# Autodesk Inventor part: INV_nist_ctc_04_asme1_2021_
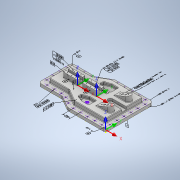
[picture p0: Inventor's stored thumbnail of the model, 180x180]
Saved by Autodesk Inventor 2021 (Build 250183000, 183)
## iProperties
Created: 2016-11
Part Number: INV_nist_ctc_04_asme1_2021_
Material: Generic
Document SubType Name: Modeling
Designer: t_liuje
Density: 1 g/cm^3
Appearance: Default
Author: t_liuje
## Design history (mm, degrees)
sketch "Sketch1"
  geometry: L1 (0, 0)-(-400.096, 0); L2 (-780, 75)-(-780, 425); L3 (-400.096, 500)-(0, 500); L4 (0, 500)-(0, 0); L5 (-400.096, 500)-(-530, 425); L6 (-400.096, 500)-(-250.096, 500); L7 (-530, 425)-(-780, 425); L8 (-400.096, 0)-(-530, 75); L9 (-530, 75)-(-780, 75)
  constraints: 18 end point, 4 horizontal, 3 equal length, 2 parallel, 1 perpendicular
  dimensions: "d5" = 780 distance between parallel lines of L4 L2; "d10" = 500 distance of L3.end L1.start; "d11" = 350 distance of L2.start L2.end; "d12" = 150 deg angle of L5 L7; "d13" = 150 deg angle of L9 L8 (= d12); "d14" = 250 distance of L8.end L2.start
extrude "Extrusion1" new body sketch "Sketch1" distance "d15" = 30; taper "d16" = 0 deg
sketch "Sketch2"
  geometry: L1 (-780, 425)-(-780, 75) reference; L2 (-780, 75)-(-530, 75) reference; L3 (-530, 75)-(-400.096, 0) reference; L4 (-400.096, 0)-(0, 0) reference; L5 (0, 0)-(0, 500) reference; L6 (0, 500)-(-400.096, 500) reference; L7 (-400.096, 500)-(-530, 425) reference; L8 (-530, 425)-(-780, 425) reference; L9 (-385.359, 445)-(-55, 445); L10 (-55, 445)-(-55, 55); L11 (-55, 55)-(-385.359, 55); L12 (-385.359, 55)-(-515.263, 130); L13 (-515.263, 130)-(-725, 130); L14 (-725, 130)-(-725, 370); L15 (-725, 370)-(-515.263, 370); L16 (-515.263, 370)-(-385.359, 445)
  constraints: 16 end point, 7 other
  dimensions: "d28" = 55 distance between parallel lines of L6 L9
extrude "Extrusion2" join sketch "Sketch2" distance "d29" = 40; taper "d30" = 0 deg
sketch "Sketch3"
  geometry: L1 (-655, 290)-(-505, 290); L2 (-505, 290)-(-505, 210); L3 (-505, 210)-(-655, 210); L4 (-655, 210)-(-655, 290); L5 (-455, 290)-(-305, 290); L6 (-305, 290)-(-305, 210); L7 (-305, 210)-(-455, 210); L8 (-455, 210)-(-455, 290); L9 (-780, 425)-(-780, 75) reference; L10 (-530, 425)-(-780, 425) reference; 1 further point
  constraints: 16 end point, 4 parallel, 2 horizontal, 2 perpendicular, 1 collinear
  dimensions: "d31" = 150 distance of L2.end L3.end; "d32" = 80 distance of L1.end L2.end; "d33" = 150 distance of L6.end L7.end (= d31); "d34" = 80 distance of L5.end L6.end (= d32); "d35" = 50 distance between parallel lines of L8 L2; "d36" = 125 distance between parallel lines of L9 L4; "d37" = 135 distance between parallel lines of L1 L10
extrude "Extrusion3" join sketch "Sketch3" distance "d38" = 50; taper "d39" = 0 deg
workplane "Work Plane2"
  workaxis "Work Axis1"
sketch "Sketch4"
  geometry: L1 (-225, 375)-(-105, 375); L2 (-105, 315)-(-225, 315); L3 (-225, 315)-(-225, 375); L4 (0, 0)-(0, 500) reference; L5 (0, 500)-(-400.096, 500) reference; L6 (-400.096, 0)-(0, 0) reference; L7 (-225, 185)-(-105, 185); L8 (-105, 125)-(-225, 125); L9 (-225, 125)-(-225, 185); A1 r 30 centre (-105, 345) between (-105, 315) and (-105, 375); A2 r 30 centre (-105, 155) between (-105, 125) and (-105, 185)
  constraints: 12 end point, 4 point on circle, 4 tangent, 2 centre point, 2 horizontal, 2 parallel
  dimensions: "d42" = 60 distance of L2.end L1.start; "d46" = 225 distance between parallel lines of L4 L3; "d47" = 120 distance from line of A1.centre L3; "d51" = 125 distance between parallel lines of L1 L5; "d54" = 60 distance of L8.end L7.start (= d42); "d55" = 120 distance from line of L9 A2.centre (= d47); "d56" = 125 distance between parallel lines of L6 L8 (= d51); "d57" = 225 distance between parallel lines of L4 L9 (= d46)
extrude "Extrusion4" join sketch "Sketch4" stored distance "d58" = 0; taper "d59" = 0 deg
sketch "Sketch5"
  geometry: L1 (-338.059, 171)-(-273, 171); L2 (-273, 171)-(-273, 96); L3 (-273, 96)-(-338.059, 96); L4 (-403, 117.981)-(-403, 149.019); L5 (-338.059, 96)-(-403, 117.981); L6 (-338.059, 171)-(-403, 149.019); L7 (-385.359, 55)-(-55, 55) reference; L8 (-55, 55)-(-55, 445) reference; L9 (-338.059, 404)-(-403, 382.019); L10 (-338.059, 404)-(-273, 404); L11 (-273, 404)-(-273, 329); L12 (-273, 329)-(-338.059, 329); L13 (-338.059, 329)-(-403, 350.981); L14 (-403, 350.981)-(-403, 382.019); L15 (-55, 445)-(-385.359, 445) reference; 1 further point
  constraints: 24 end point, 6 parallel, 2 horizontal, 2 perpendicular
  dimensions: "d61" = 75 distance of L1.end L2.end; "d62" = 161.3 deg angle of L1 L6; "d63" = 161.3 deg angle of L3 L5 (= d62); "d64" = 130 distance between parallel lines of L2 L4; "d65" = 65.059 distance of L1.start L1.end; "d66" = 41 distance between parallel lines of L3 L7; "d68" = 75 distance of L10.end L11.end; "d69" = 161.3 deg angle of L10 L9; "d70" = 161.3 deg angle of L12 L13 (= d69); "d71" = 130 distance between parallel lines of L11 L14; "d72" = 65.059 distance of L9.start L10.end; "d73" = 218 distance between parallel lines of L8 L2; "d74" = 218 distance between parallel lines of L8 L11 (= d73); "d75" = 41 distance between parallel lines of L10 L15 (= d66)
extrude "Extrusion5" cut sketch "Sketch5" distance "d76" = 26.25; taper "d77" = 0 deg
fillet "Fillet2" dims "d92" = 4
fillet "Fillet8" dims "d93" = 13
fillet "Fillet9" dims "d94" = 25
fillet "Fillet10" dims "d95" = 5
sketch "Sketch6"
  geometry: L1 (-200, 275)-(-55, 275); L2 (-55, 275)-(-55, 225); L3 (-55, 225)-(-200, 225); L4 (-381.876, 55)-(-68, 55) reference; L5 (-55, 68)-(-55, 432) reference; A1 r 25 centre (-200, 250) between (-200, 275) and (-200, 225); 1 further point
  constraints: 6 end point, 2 point on circle, 2 tangent, 1 centre point, 1 collinear, 1 horizontal, 1 parallel, 1 perpendicular
  dimensions: "d98" = 170 distance between parallel lines of L4 L3; "d99" = 145 distance from line of L2 A1.centre; "d100" = 50 distance between parallel lines of L3 L1
extrude "Extrusion6" cut sketch "Sketch6" distance "d101" = 25.125; taper "d102" = 0 deg
fillet "Fillet11" dims "d103" = 2.5
workplane "Work Plane3"
sketch "Sketch13"
  geometry: 31 further points
sketch "Sketch7"
  geometry: L1 (129.424, 5)-(13.347, 5); L2 (129.424, 255)-(13.347, 255); 11 further points
  constraints: 4 end point, 2 coincident
  dimensions: "d188" = 95 distance of point (129.424, 35) point (34.424, 35); "d189" = 30 distance from line of L1 point (34.424, 35); "d190" = 30 distance of point (129.424, 35) point (99.424, 35); "d191" = 35 distance of point (64.424, 35) point (99.424, 35)
sketch "Sketch14"
  geometry: A1 r 25 centre (755, 400) between (780, 400) and (755, 425) reference; 33 further points
  constraints: 1 coincident
hole "Hole22" sketch "Sketch14" diameter "d754" = 14; stored, may be unused: countersink angle "d758" = 90 deg, drill point angle "d760" = 118 deg; dims "d755" = 6, "d756" = 20, "d757" = 2, "d759" = 8
hole "Hole8" sketch "Sketch7" diameter "d172" = 10.106; stored, may be unused: countersink angle "d176" = 90 deg, drill point angle "d178" = 118 deg; dims "d173" = 25, "d174" = 4, "d175" = 2, "d177" = 25
hole "Hole10" sketch "Sketch7" diameter "d192" = 12; stored, may be unused: countersink angle "d196" = 90 deg, drill point angle "d198" = 118 deg; dims "d193" = 6, "d194" = 20, "d195" = 20, "d197" = 40.2
hole "Hole20" sketch "Sketch14" diameter "d678" = 14; stored, may be unused: countersink angle "d682" = 90 deg, drill point angle "d684" = 118 deg; dims "d679" = 6, "d680" = 20, "d681" = 2, "d683" = 8
hole "Hole21" sketch "Sketch14" diameter "d747" = 14; stored, may be unused: countersink angle "d751" = 90 deg, drill point angle "d753" = 118 deg; dims "d748" = 6, "d749" = 20, "d750" = 2, "d752" = 8
sketch "Sketch8"
  geometry: L1 (-671.016, 276.25)-(-285.042, 276.25); L2 (-671.016, 223.75)-(-285.042, 223.75); L3 (-625, 310.911)-(-625, 176.517); L4 (-580, 310.911)-(-580, 176.517); L5 (-535, 310.911)-(-535, 182.097); L6 (-425, 310.911)-(-425, 188.608); L7 (-380, 307.655)-(-380, 193.258); L8 (-335, 307.655)-(-335, 188.608); L9 (-655, 286)-(-655, 214) reference; L10 (-455, 286)-(-455, 214) reference; L11 (-651, 210)-(-509, 210) reference; 13 further points
  constraints: 24 point on line, 16 end point, 6 vertical, 2 horizontal
  dimensions: "d199" = 30 distance between parallel lines of L9 L3; "d200" = 45 distance between parallel lines of L4 L3; "d201" = 45 distance between parallel lines of L5 L4; "d202" = 30 distance between parallel lines of L10 L6; "d203" = 45 distance between parallel lines of L7 L6; "d204" = 45 distance between parallel lines of L8 L7; "d205" = 13.75 distance between parallel lines of L11 L2; "d206" = 52.5 distance between parallel lines of L2 L1
hole "Hole11" sketch "Sketch8" diameter "d207" = 6.647; stored, may be unused: countersink angle "d211" = 90 deg, drill point angle "d213" = 118 deg; dims "d208" = 6, "d209" = 20, "d210" = 20, "d212" = 25
hole "Hole19" sketch "Sketch8" diameter "d659" = 6.647; stored, may be unused: countersink angle "d663" = 90 deg, drill point angle "d665" = 118 deg; dims "d660" = 6, "d661" = 4, "d662" = 2, "d664" = 25
sketch "Sketch9"
  geometry: L1 (46, 48.5)-(21, 48.5); L2 (21, 23.5)-(46, 23.5); L3 (46, 23.5)-(46, 48.5); L4 (46, 76)-(0, 76) reference; L5 (46, 72)-(46, 0) reference; A1 r 12.5 centre (21, 36) between (21, 48.5) and (21, 23.5); 1 further point
  constraints: 6 end point, 2 point on circle, 2 tangent, 1 centre point, 1 collinear, 1 horizontal, 1 parallel
  dimensions: "d215" = 25 distance of L2.start L1.end; "d216" = 27.5 distance between parallel lines of L4 L1; "d218" = 25 distance from line of A1.centre L3
extrude "Extrusion7" cut sketch "Sketch9" stored distance "d219" = 25.125; taper "d220" = 0 deg
hole "Hole12" diameter "d223" = 10; stored, may be unused: countersink angle "d227" = 90 deg, drill point angle "d229" = 118 deg; dims "d221" = 12, "d222" = 52.5, "d224" = 6, "d225" = 20, "d226" = 20, "d228" = 25
hole "Hole13" diameter "d232" = 10; stored, may be unused: countersink angle "d236" = 90 deg, drill point angle "d238" = 118 deg; dims "d230" = 12, "d231" = 52.5, "d233" = 6, "d234" = 20, "d235" = 20, "d237" = 25
sketch "Sketch10"
  geometry: L1 (25, 0)-(393.397, 0) reference; L2 (405.897, 3.349)-(524.199, 71.651) reference; L3 (536.699, 75)-(755, 75) reference; L4 (780, 100)-(780, 400) reference; L5 (755, 425)-(536.699, 425) reference; L6 (393.397, 500)-(25, 500) reference; L7 (524.199, 428.349)-(405.897, 496.651) reference; L8 (0, 475)-(0, 25) reference; L9 (87.702, 70)-(379.404, 70); L10 (491.987, 135)-(687.702, 135); L11 (87.702, 210)-(687.702, 210); L12 (87.702, 210)-(87.702, 70); L13 (687.702, 210)-(687.702, 135); L14 (379.404, 70)-(491.987, 135); 1 further point
  constraints: 12 end point, 8 point on line, 4 parallel, 2 vertical
  dimensions: "d242" = 70 distance between parallel lines of L1 L9; "d243" = 60 distance between parallel lines of L3 L10; "d244" = 75 distance between parallel lines of L10 L11; "d245" = 87.702 distance between parallel lines of L8 L12; "d246" = 92.298 distance between parallel lines of L4 L13; "d247" = 70.968 distance between parallel lines of L2 L14
extrude "Extrusion8" cut sketch "Sketch10" distance "d248" = 15.811; taper "d249" = 0 deg
fillet "Fillet12" dims "d250" = 5
mirror "Mirror2"
sketch "Sketch11"
  geometry: L1 (-341.146, 145.064)-(-319.933, 123.851); L2 (-336.018, 148.422)-(-316.576, 128.979); L3 (-328.418, 149.307)-(-315.691, 136.579); L4 (-344.504, 139.936)-(-325.061, 120.494); L5 (-345.389, 132.337)-(-332.661, 119.609); 1 further point
  constraints: 10 end point, 1 midpoint, 12 other
body "Solid1"
node "Annotations"
node "Tolerance Features"
fillet "Fillet1" dims "d81" = 5
chamfer "Chamfer1" distance "d89" = 5; stored, may be unused: second distance "d90" = 2, angle "d91" = 45 deg
node "Projected Loop1"
workplane "Work Plane1"
node "Planar Surface 1" dims "d269" = 9.58338 (derived), "d270" = 5.20441 (derived), "d342" = 29.35731 (derived), "d343" = 1.74635 (derived), "d344" = -3.74843 (derived), "d345" = 10 (derived), "d642" = 28.40977 (derived), "d690" = 909.09523 (derived), "d691" = 910.05054 (derived), "d692" = 75 (derived), "d774" = 8.55047 (derived), "d775" = 6.5519 (derived), "d776" = 0.5 (derived), "d777" = 0 (derived), "d778" = 0 (derived), "d786" = 19.57161 (derived), "d787" = 5 (derived), "d788" = 1 (derived), "d790" = 0.75 (derived), "d791" = 50 (derived), "d792" = 0 (derived), "d793" = 3.45907 (derived), "d794" = 2.53074 (derived), "d795" = 5.54765 (derived)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
node "Datum Identifier 1" dims "d269" = 9.58338 (derived), "d270" = 5.20441 (derived), "d342" = 29.35731 (derived), "d343" = 1.74635 (derived), "d344" = -3.74843 (derived), "d345" = 10 (derived), "d642" = 28.40977 (derived), "d678" = 14, "d690" = 909.09523 (derived), "d691" = 910.05054 (derived), "d692" = 75 (derived), "d747" = 14, "d754" = 14, "d774" = 8.55047 (derived), "d775" = 6.5519 (derived), "d776" = 0.5 (derived), "d777" = 0 (derived), "d778" = 0 (derived), "d786" = 19.57161 (derived), "d787" = 5 (derived), "d788" = 1 (derived), "d790" = 0.75 (derived), "d791" = 50 (derived), "d792" = 0 (derived)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
node "Datum Reference Frame 1"
node "Diameter Dimension 3" dims "d345" = 10 (derived)
node "Coplanar Group 1"
node "Parallel Axes Pattern 14"
node "Hole Note 31"
node "Linear Dimension 1" dims "d692" = 75 (derived)
node "Simple Hole 185" dims "d269" = 9.58338 (derived), "d270" = 5.20441 (derived), "d342" = 29.35731 (derived), "d343" = 1.74635 (derived), "d344" = -3.74843 (derived), "d345" = 10 (derived), "d642" = 28.40977 (derived), "d690" = 909.09523 (derived), "d691" = 910.05054 (derived), "d692" = 75 (derived), "d774" = 8.55047 (derived), "d775" = 6.5519 (derived), "d776" = 0.5 (derived), "d777" = 0 (derived), "d778" = 0 (derived), "d786" = 19.57161 (derived), "d787" = 5 (derived), "d788" = 1 (derived), "d790" = 0.75 (derived), "d791" = 50 (derived), "d792" = 0 (derived), "d793" = 3.45907 (derived), "d794" = 2.53074 (derived), "d795" = 5.54765 (derived)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
node "Datum Reference Frame 22"
node "Simple Hole 186" dims "d269" = 9.58338 (derived), "d270" = 5.20441 (derived), "d342" = 29.35731 (derived), "d343" = 1.74635 (derived), "d344" = -3.74843 (derived), "d345" = 10 (derived), "d642" = 28.40977 (derived), "d690" = 909.09523 (derived), "d691" = 910.05054 (derived), "d692" = 75 (derived), "d774" = 8.55047 (derived), "d775" = 6.5519 (derived), "d776" = 0.5 (derived), "d777" = 0 (derived), "d778" = 0 (derived), "d786" = 19.57161 (derived), "d787" = 5 (derived), "d788" = 1 (derived), "d790" = 0.75 (derived), "d791" = 50 (derived), "d792" = 0 (derived), "d793" = 3.45907 (derived), "d794" = 2.53074 (derived), "d795" = 5.54765 (derived)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
node "Datum Reference Frame 23"
node "Datum Reference Frame 24"
node "Planar Surface 15"
node "Feature Control Frame 1"
node "Simple Hole 187"
node "Simple Hole 188"
node "Simple Hole 189"
node "Simple Hole 190"
node "Simple Hole 191"
node "Hole Note 32"
node "Feature Control Frame 3"
node "Planar Surface 16" dims "d269" = 9.58338 (derived), "d270" = 5.20441 (derived), "d342" = 29.35731 (derived), "d343" = 1.74635 (derived), "d344" = -3.74843 (derived), "d345" = 10 (derived), "d642" = 28.40977 (derived), "d690" = 909.09523 (derived), "d691" = 910.05054 (derived), "d692" = 75 (derived), "d774" = 8.55047 (derived), "d775" = 6.5519 (derived), "d776" = 0.5 (derived), "d777" = 0 (derived), "d778" = 0 (derived), "d786" = 19.57161 (derived), "d787" = 5 (derived), "d788" = 1 (derived), "d790" = 0.75 (derived), "d791" = 50 (derived), "d792" = 0 (derived), "d793" = 3.45907 (derived), "d794" = 2.53074 (derived), "d795" = 5.54765 (derived)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
node "Datum Identifier 19" dims "d269" = 9.58338 (derived), "d270" = 5.20441 (derived), "d342" = 29.35731 (derived), "d343" = 1.74635 (derived), "d344" = -3.74843 (derived), "d345" = 10 (derived), "d642" = 28.40977 (derived), "d678" = 14, "d690" = 909.09523 (derived), "d691" = 910.05054 (derived), "d692" = 75 (derived), "d747" = 14, "d754" = 14, "d774" = 8.55047 (derived), "d775" = 6.5519 (derived), "d776" = 0.5 (derived), "d777" = 0 (derived), "d778" = 0 (derived), "d786" = 19.57161 (derived), "d787" = 5 (derived), "d788" = 1 (derived), "d790" = 0.75 (derived), "d791" = 50 (derived), "d792" = 0 (derived)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
node "Datum Reference Frame 25"
node "Planar Surface 17" dims "d269" = 9.58338 (derived), "d270" = 5.20441 (derived), "d342" = 29.35731 (derived), "d343" = 1.74635 (derived), "d344" = -3.74843 (derived), "d345" = 10 (derived), "d642" = 28.40977 (derived), "d690" = 909.09523 (derived), "d691" = 910.05054 (derived), "d692" = 75 (derived), "d774" = 8.55047 (derived), "d775" = 6.5519 (derived), "d776" = 0.5 (derived), "d777" = 0 (derived), "d778" = 0 (derived), "d786" = 19.57161 (derived), "d787" = 5 (derived), "d788" = 1 (derived), "d790" = 0.75 (derived), "d791" = 50 (derived), "d792" = 0 (derived), "d793" = 3.45907 (derived), "d794" = 2.53074 (derived), "d795" = 5.54765 (derived)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
node "Datum Identifier 20" dims "d269" = 9.58338 (derived), "d270" = 5.20441 (derived), "d342" = 29.35731 (derived), "d343" = 1.74635 (derived), "d344" = -3.74843 (derived), "d345" = 10 (derived), "d642" = 28.40977 (derived), "d678" = 14, "d690" = 909.09523 (derived), "d691" = 910.05054 (derived), "d692" = 75 (derived), "d747" = 14, "d754" = 14, "d774" = 8.55047 (derived), "d775" = 6.5519 (derived), "d776" = 0.5 (derived), "d777" = 0 (derived), "d778" = 0 (derived), "d786" = 19.57161 (derived), "d787" = 5 (derived), "d788" = 1 (derived), "d790" = 0.75 (derived), "d791" = 50 (derived), "d792" = 0 (derived)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
node "Datum Reference Frame 26"
node "Planar Surface 18" dims "d269" = 9.58338 (derived), "d270" = 5.20441 (derived), "d342" = 29.35731 (derived), "d343" = 1.74635 (derived), "d344" = -3.74843 (derived), "d345" = 10 (derived), "d642" = 28.40977 (derived), "d690" = 909.09523 (derived), "d691" = 910.05054 (derived), "d692" = 75 (derived), "d774" = 8.55047 (derived), "d775" = 6.5519 (derived), "d776" = 0.5 (derived), "d777" = 0 (derived), "d778" = 0 (derived), "d786" = 19.57161 (derived), "d787" = 5 (derived), "d788" = 1 (derived), "d790" = 0.75 (derived), "d791" = 50 (derived), "d792" = 0 (derived), "d793" = 3.45907 (derived), "d794" = 2.53074 (derived), "d795" = 5.54765 (derived)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
node "Datum Identifier 21" dims "d269" = 9.58338 (derived), "d270" = 5.20441 (derived), "d342" = 29.35731 (derived), "d343" = 1.74635 (derived), "d344" = -3.74843 (derived), "d345" = 10 (derived), "d642" = 28.40977 (derived), "d678" = 14, "d690" = 909.09523 (derived), "d691" = 910.05054 (derived), "d692" = 75 (derived), "d747" = 14, "d754" = 14, "d774" = 8.55047 (derived), "d775" = 6.5519 (derived), "d776" = 0.5 (derived), "d777" = 0 (derived), "d778" = 0 (derived), "d786" = 19.57161 (derived), "d787" = 5 (derived), "d788" = 1 (derived), "d790" = 0.75 (derived), "d791" = 50 (derived), "d792" = 0 (derived)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
node "Datum Reference Frame 27"
node "Planar Surface 19" dims "d269" = 9.58338 (derived), "d270" = 5.20441 (derived), "d342" = 29.35731 (derived), "d343" = 1.74635 (derived), "d344" = -3.74843 (derived), "d345" = 10 (derived), "d642" = 28.40977 (derived), "d690" = 909.09523 (derived), "d691" = 910.05054 (derived), "d692" = 75 (derived), "d774" = 8.55047 (derived), "d775" = 6.5519 (derived), "d776" = 0.5 (derived), "d777" = 0 (derived), "d778" = 0 (derived), "d786" = 19.57161 (derived), "d787" = 5 (derived), "d788" = 1 (derived), "d790" = 0.75 (derived), "d791" = 50 (derived), "d792" = 0 (derived), "d793" = 3.45907 (derived), "d794" = 2.53074 (derived), "d795" = 5.54765 (derived)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
node "Datum Identifier 22" dims "d269" = 9.58338 (derived), "d270" = 5.20441 (derived), "d342" = 29.35731 (derived), "d343" = 1.74635 (derived), "d344" = -3.74843 (derived), "d345" = 10 (derived), "d642" = 28.40977 (derived), "d678" = 14, "d690" = 909.09523 (derived), "d691" = 910.05054 (derived), "d692" = 75 (derived), "d747" = 14, "d754" = 14, "d774" = 8.55047 (derived), "d775" = 6.5519 (derived), "d776" = 0.5 (derived), "d777" = 0 (derived), "d778" = 0 (derived), "d786" = 19.57161 (derived), "d787" = 5 (derived), "d788" = 1 (derived), "d790" = 0.75 (derived), "d791" = 50 (derived), "d792" = 0 (derived)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
node "Datum Reference Frame 28"
node "Planar Surface 20" dims "d269" = 9.58338 (derived), "d270" = 5.20441 (derived), "d342" = 29.35731 (derived), "d343" = 1.74635 (derived), "d344" = -3.74843 (derived), "d345" = 10 (derived), "d642" = 28.40977 (derived), "d690" = 909.09523 (derived), "d691" = 910.05054 (derived), "d692" = 75 (derived), "d774" = 8.55047 (derived), "d775" = 6.5519 (derived), "d776" = 0.5 (derived), "d777" = 0 (derived), "d778" = 0 (derived), "d786" = 19.57161 (derived), "d787" = 5 (derived), "d788" = 1 (derived), "d790" = 0.75 (derived), "d791" = 50 (derived), "d792" = 0 (derived), "d793" = 3.45907 (derived), "d794" = 2.53074 (derived), "d795" = 5.54765 (derived)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
node "Datum Identifier 23" dims "d269" = 9.58338 (derived), "d270" = 5.20441 (derived), "d342" = 29.35731 (derived), "d343" = 1.74635 (derived), "d344" = -3.74843 (derived), "d345" = 10 (derived), "d642" = 28.40977 (derived), "d678" = 14, "d690" = 909.09523 (derived), "d691" = 910.05054 (derived), "d692" = 75 (derived), "d747" = 14, "d754" = 14, "d774" = 8.55047 (derived), "d775" = 6.5519 (derived), "d776" = 0.5 (derived), "d777" = 0 (derived), "d778" = 0 (derived), "d786" = 19.57161 (derived), "d787" = 5 (derived), "d788" = 1 (derived), "d790" = 0.75 (derived), "d791" = 50 (derived), "d792" = 0 (derived)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
node "Datum Reference Frame 29"
node "Datum Reference Frame 30"
node "Datum Reference Frame 31"
node "Datum Reference Frame 32"
node "Simple Hole 192"
node "Simple Hole 193"
node "Simple Hole 194"
node "Simple Hole 195"
node "Simple Hole 196"
node "Simple Hole 197"
node "Parallel Axes Pattern 15"
node "Hole Note 33"
node "Feature Control Frame 4"
node "Planar Surface 21"
node "Planar Surface 22"
node "Feature Control Frame 5"
node "Leader Text 1"
node "Hole Note 34"
node "Hole Note 35"
node "Diameter Dimension 9" dims "d847" = 14 (derived)
node "Datum Identifier 26" dims "d269" = 9.58338 (derived), "d270" = 5.20441 (derived), "d342" = 29.35731 (derived), "d343" = 1.74635 (derived), "d344" = -3.74843 (derived), "d345" = 10 (derived), "d642" = 28.40977 (derived), "d678" = 14, "d690" = 909.09523 (derived), "d691" = 910.05054 (derived), "d692" = 75 (derived), "d747" = 14, "d754" = 14, "d774" = 8.55047 (derived), "d775" = 6.5519 (derived), "d776" = 0.5 (derived), "d777" = 0 (derived), "d778" = 0 (derived), "d786" = 19.57161 (derived), "d787" = 5 (derived), "d788" = 1 (derived), "d790" = 0.75 (derived), "d791" = 50 (derived), "d792" = 0 (derived)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
node "Diameter Dimension 10" dims "d851" = 14 (derived)
node "Feature Control Frame 6"
node "Diameter Dimension 8" dims "d858" = 14 (derived)
node "Datum Identifier 27" dims "d269" = 9.58338 (derived), "d270" = 5.20441 (derived), "d342" = 29.35731 (derived), "d343" = 1.74635 (derived), "d344" = -3.74843 (derived), "d345" = 10 (derived), "d642" = 28.40977 (derived), "d678" = 14, "d690" = 909.09523 (derived), "d691" = 910.05054 (derived), "d692" = 75 (derived), "d747" = 14, "d754" = 14, "d774" = 8.55047 (derived), "d775" = 6.5519 (derived), "d776" = 0.5 (derived), "d777" = 0 (derived), "d778" = 0 (derived), "d786" = 19.57161 (derived), "d787" = 5 (derived), "d788" = 1 (derived), "d790" = 0.75 (derived), "d791" = 50 (derived), "d792" = 0 (derived)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
other parameters: "d40" = -225, "d41" = 22 deg, "d180" = 1, "d347" = 0, "d348" = 0, "d349" = 0, "d350" = 0, "d351" = 0, "d352" = 0, "d353" = 0, "d354" = -4, "d355" = 0, "d356" = 0, "d357" = 0, "d358" = 0, "d359" = 0, "d360" = -4, "d361" = 0, "d362" = 0, "d363" = 0, "d364" = 0
